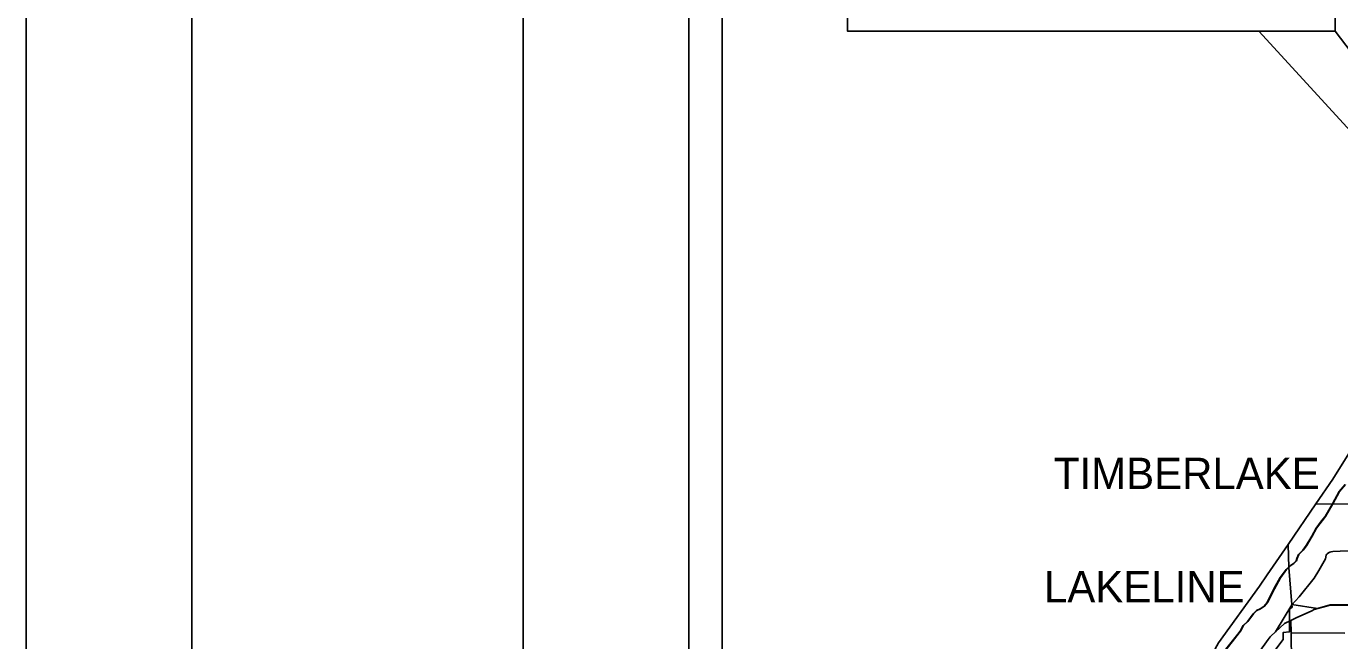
# Model space of a CAD drawing. Extents: x 0 to 34, y 0 to 22.
# Drawn here: x 0 to 3.964, y 16.121 to 17.975 of the extents above; entities that cross this region are included whole.
import ezdxf

# ---------------------------------------------------------------- set-up
doc = ezdxf.new("R2010")
doc.units = 0
for name, color, linetype in [('GM_X_City_Street', 7, 'Continuous'), ('GM_X_Corporation', 7, 'Continuous'), ('GM_X_Corporation_Text', 7, 'Continuous'), ('GM_X_County_Road', 7, 'Continuous'), ('GM_X_Major_Lake', 7, 'Continuous'), ('GM_X_State_Route', 7, 'Continuous'), ('SH_Border', 7, 'Continuous'), ('SH_Cut_Line', 7, 'Continuous'), ('SH_Data', 7, 'Continuous'), ('SH_Text', 7, 'Continuous')]:
    doc.layers.add(name, color=color, linetype=linetype)

msp = doc.modelspace()

# ---------------------------------------------------------------- linework, layer by layer
at = {"layer": 'GM_X_City_Street'}
for p, q in [((3.7705, 16.1481), (3.8197, 16.2293)), ((3.8171, 16.1447), (3.9789, 16.1436))]:
    msp.add_line(p, q, dxfattribs=at)
msp.add_lwpolyline([(3.8197, 16.2293), (3.8415, 16.2536), (3.8871, 16.3097), (3.9006, 16.3329), (3.9206, 16.368), (3.9231, 16.379), (3.9241, 16.3806), (3.9261, 16.383), (3.93, 16.3855), (3.9345, 16.388), (3.9379, 16.3893), (3.9428, 16.3901), (3.9652, 16.3909), (4.0805, 16.3947), (4.2068, 16.3973), (4.2091, 16.3973), (4.2107, 16.3973), (4.3996, 16.4041), (4.4727, 16.4081)], dxfattribs=at)
at = {"layer": 'GM_X_Corporation'}
for points in [[(4.0401, 16.7629), (3.9431, 16.6079), (3.8922, 16.5335), (4.2786, 16.5303)], [(3.9801, 16.5923), (3.9624, 16.5708), (3.9419, 16.5334), (3.9202, 16.496), (3.9094, 16.4828), (3.8929, 16.4605), (3.8793, 16.4359), (3.8627, 16.4076), (3.8526, 16.394), (3.8392, 16.3808), (3.8349, 16.3687), (3.8322, 16.3623), (3.8248, 16.3536), (3.8157, 16.348), (3.8019, 16.336), (3.7845, 16.3111), (3.7655, 16.277), (3.745, 16.2366), (3.7357, 16.2249), (3.7235, 16.217), (3.7124, 16.2118), (3.7024, 16.202), (3.6943, 16.1907), (3.6855, 16.1786), (3.6724, 16.1666), (3.6635, 16.15), (3.6523, 16.1356), (3.62, 16.0949)], [(3.9801, 16.5923), (3.9624, 16.5708), (3.9419, 16.5334), (3.9202, 16.496), (3.9094, 16.4828), (3.8929, 16.4605), (3.8793, 16.4359), (3.8627, 16.4076), (3.8526, 16.394), (3.8392, 16.3808), (3.8349, 16.3687), (3.8322, 16.3623), (3.8248, 16.3536), (3.8157, 16.348), (3.8019, 16.336), (3.7845, 16.3111), (3.7655, 16.277), (3.745, 16.2366), (3.7357, 16.2249), (3.7235, 16.217), (3.7124, 16.2118), (3.7024, 16.202), (3.6943, 16.1907), (3.6855, 16.1786), (3.6724, 16.1666), (3.6635, 16.15), (3.6523, 16.1356), (3.62, 16.0949)], [(4.085, 16.2301), (3.9352, 16.2287), (3.8967, 16.2178), (3.8193, 16.2299), (3.8194, 16.2292), (3.82, 16.2216), (3.8121, 16.2158), (3.8124, 16.1478), (3.7931, 16.1456), (3.793, 16.1244), (3.6886, 15.9861)]]:
    msp.add_lwpolyline(points, dxfattribs=at)
for points in [[(3.8084, 16.4111), (3.8922, 16.5335), (4.2786, 16.5303), (4.4988, 16.5299), (4.5461, 16.5283), (4.5513, 16.4904), (4.5873, 16.4879), (4.5769, 16.4486), (4.5651, 16.4021), (4.5587, 16.3754), (4.5511, 16.3016), (4.5471, 16.2647), (4.5436, 16.2259), (4.3148, 16.2298), (4.085, 16.2301), (3.9352, 16.2287), (3.8967, 16.2178), (3.8193, 16.2299), (3.8106, 16.3415)], [(3.379, 15.7868), (3.4395, 15.8848), (3.5063, 15.9488), (3.5977, 16.1143), (3.7217, 16.2854), (3.7454, 16.3198), (3.8084, 16.4111), (3.8106, 16.3415), (3.8193, 16.2299), (3.8194, 16.2292), (3.82, 16.2216), (3.8121, 16.2158), (3.8124, 16.1478), (3.7931, 16.1456), (3.793, 16.1244), (3.6886, 15.9861), (3.6694, 15.9766), (3.6692, 15.9536), (3.625, 15.9541), (3.6858, 15.8929), (3.5109, 15.6585)]]:
    msp.add_lwpolyline(points, close=True, dxfattribs=at)
at = {"layer": 'GM_X_County_Road'}
msp.add_lwpolyline([(3.8346, 15.699), (3.8309, 15.7836), (3.8243, 15.8547), (3.8237, 15.9094), (3.8226, 15.9466), (3.8207, 16.0086), (3.8185, 16.0804), (3.818, 16.0983), (3.8179, 16.1024), (3.8171, 16.1447), (3.8165, 16.1821)], dxfattribs=at)
at = {"layer": 'GM_X_Major_Lake'}
msp.add_lwpolyline([(3.621, 16.0948), (3.6534, 16.1356), (3.6646, 16.1499), (3.6735, 16.1665), (3.6865, 16.1786), (3.6954, 16.1906), (3.7035, 16.202), (3.7135, 16.2118), (3.7245, 16.217), (3.7368, 16.2248), (3.746, 16.2365), (3.7666, 16.277), (3.7856, 16.311), (3.8029, 16.3359), (3.8167, 16.3479), (3.8259, 16.3536), (3.8332, 16.3622), (3.8359, 16.3687), (3.8403, 16.3808), (3.8537, 16.394), (3.8637, 16.4075), (3.8804, 16.4359), (3.8939, 16.4605), (3.9105, 16.4827), (3.9213, 16.4959), (3.9429, 16.5333), (3.9635, 16.5708), (3.9812, 16.5923)], dxfattribs=at)
at = {"layer": 'GM_X_State_Route'}
for points in [[(3.88, 16.2112), (3.8873, 16.2146), (3.9354, 16.2281), (3.968, 16.2281), (3.9853, 16.2281), (3.9967, 16.2281)], [(3.7559, 16.1342), (3.7705, 16.1481), (3.797, 16.1732), (3.8165, 16.1821), (3.8241, 16.1856), (3.8349, 16.1905)], [(3.8349, 16.1905), (3.8782, 16.2104), (3.88, 16.2112)], [(3.4522, 15.7159), (3.5614, 15.8628), (3.6058, 15.9277), (3.6252, 15.9535), (3.748, 16.124), (3.7544, 16.1329), (3.7559, 16.1342)]]:
    msp.add_lwpolyline(points, dxfattribs=at)
at = {"layer": 'SH_Border'}
for points in [[(0.5, 21.5), (1.5, 21.5), (1.5, 0.5), (0.5, 0.5)], [(1.5, 21.5), (33.5, 21.5), (33.5, 0.5), (1.5, 0.5)], [(2.4787, 18.3897), (3.9503, 18.3897), (3.9503, 17.9593), (2.4787, 17.9593)]]:
    msp.add_lwpolyline(points, close=True, dxfattribs=at)
at = {"layer": 'SH_Cut_Line'}
msp.add_lwpolyline([(0, 0), (34, 0), (34, 22), (0, 22)], close=True, dxfattribs=at)
at = {"layer": 'SH_Data'}
for p, q in [((2, 21), (2, 14)), ((2.1, 20.9), (2.1, 14.1))]:
    msp.add_line(p, q, dxfattribs=at)
at = {"layer": 'SH_Text'}
msp.add_lwpolyline([(3.9503, 17.9593), (5.0861, 16.4701), (3.7201, 17.9593)], close=True, dxfattribs=at)

# ---------------------------------------------------------------- texts
at = {"layer": 'GM_X_Corporation_Text'}
for s, p in [('TIMBERLAKE', (3.1013, 16.5782)), ('LAKELINE', (3.0715, 16.2365))]:
    msp.add_text(s, height=0.0947, rotation=0, dxfattribs=at).set_placement(p)

doc.saveas('drawing.dxf')
